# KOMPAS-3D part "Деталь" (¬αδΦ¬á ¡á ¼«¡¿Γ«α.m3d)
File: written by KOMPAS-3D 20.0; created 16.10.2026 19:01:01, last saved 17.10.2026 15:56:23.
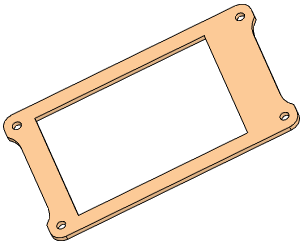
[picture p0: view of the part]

Document properties: Полное имя файла: D:\myProjects\Progect_esp32\box_compas\корпус\крышка на монитор.m3d

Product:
- Part/product: Деталь
    Масса: 0.0229921

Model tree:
1. Эскиз:1
2. Элемент выдавливания:1
     Расстояние 1 = 1.6
3. Элемент выдавливания:2
     Расстояние 1 = 1.5
4. Эскиз:2  (with: Элемент выдавливания:1)
5. Элемент выдавливания:3
     Расстояние 2 = 1.6
6. Массив по сетке:1  (with: Элемент выдавливания:3, Эскиз:2)  (4 pattern instances)
     Шаг 1 = 75.9; Угол раствора = -90; Шаг 2 = 44.2; Геометрический массив = 128
7. Эскиз:3  (with: Элемент выдавливания:1, Элемент выдавливания:3)
8. Элемент выдавливания:4
     Расстояние 2 = 1.6
9. Скругление:1  (with: Элемент выдавливания:1)
     Радиус = 4
10. Эскиз:4  (with: Элемент выдавливания:1)
11. Элемент выдавливания:5
     Расстояние 2 = 1.6
12. Смещенная плоскость:2  (with: Элемент выдавливания:1)
     Расстояние = -42
13. Зеркальный массив:1
14. Экземпляр ( 1 )
15. Экземпляр ( 2 )  (with: Элемент выдавливания:5)
16. Скругление:2  (with: Элемент выдавливания:1, Элемент выдавливания:5, Скругление:1, Элемент выдавливания:4, Элемент выдавливания:3)
     Радиус = 0.8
